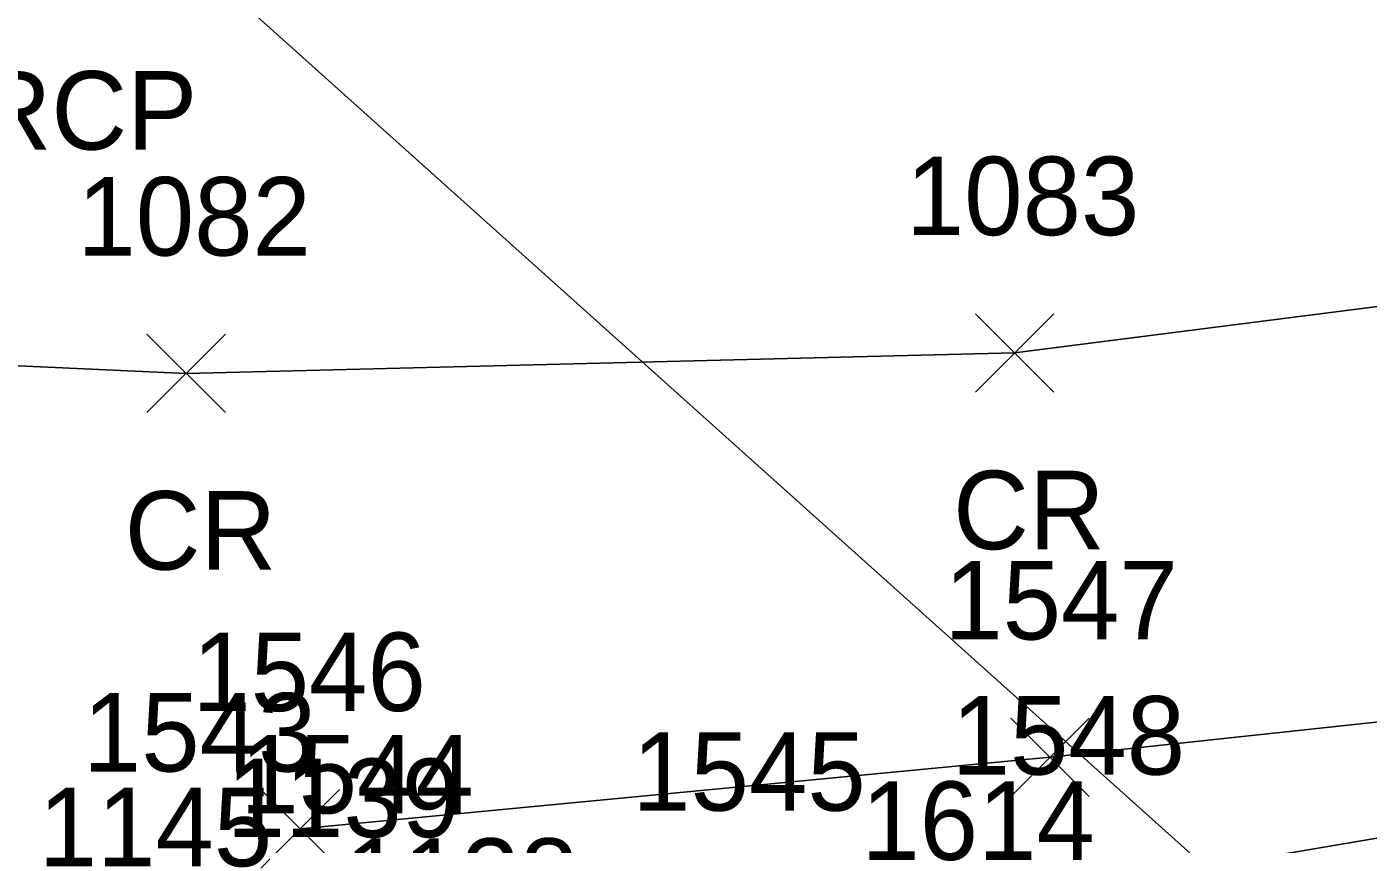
# Model space of a CAD drawing. Extents: x 1657482 to 1661439, y 647981 to 649041.
# Drawn here: x 1659845.16 to 1659879.34, y 648083.85 to 648104.67 of the extents above; entities that cross this region are included whole.
import ezdxf

# ---------------------------------------------------------------- set-up
doc = ezdxf.new("R2010")
doc.units = 0
for name, color, linetype in [('D_C', 7, 'Continuous'), ('DCP', 7, 'Continuous'), ('L_I', 7, 'Continuous'), ('P_A', 7, 'Continuous'), ('P_I', 7, 'Continuous'), ('P_TIC', 7, 'Continuous'), ('PET', 7, 'Continuous'), ('PRC', 7, 'Continuous')]:
    doc.layers.add(name, color=color, linetype=linetype)

msp = doc.modelspace()

# ---------------------------------------------------------------- linework, layer by layer
at = {"layer": 'DCP'}
msp.add_lwpolyline([(1659844.779, 648110.54), (1659890.624, 648069.43)], dxfattribs=at)
at = {"layer": 'P_TIC'}
for points in [[(1659869.331, 648095.361), (1659871.331, 648097.361)], [(1659871.331, 648095.361), (1659869.331, 648097.361)], [(1659848.225, 648094.841), (1659850.225, 648096.841)], [(1659850.225, 648094.841), (1659848.225, 648096.841)], [(1659870.232, 648085.062), (1659872.232, 648087.062)], [(1659872.232, 648085.062), (1659870.232, 648087.062)], [(1659851.129, 648083.239), (1659853.129, 648085.239)], [(1659853.129, 648083.239), (1659851.129, 648085.239)]]:
    msp.add_lwpolyline(points, dxfattribs=at)
at = {"layer": 'PET'}
msp.add_lwpolyline([(1659799.28, 648086.136), (1659822.829, 648084.094), (1659841.236, 648083.238), (1659849.285, 648082.699), (1659853.297, 648081.633), (1659863.28, 648081.701), (1659871.418, 648082.62), (1659885.552, 648085.022), (1659891.684, 648086.345), (1659901.533, 648088.7), (1659915.482, 648092.509), (1659918.893, 648092.262), (1659919.908, 648093.139), (1659925.791, 648090.399), (1659928.096, 648095.554), (1659935.247, 648097.751), (1659946.62, 648102.053), (1659958.358, 648107.252), (1659972.375, 648114.357), (1659985.018, 648121.317), (1659986.135, 648122.233), (1660002.916, 648130.398), (1660023.122, 648141.511)], dxfattribs=at)
at = {"layer": 'PRC'}
for points in [[(1659666.144, 648110.534), (1659699.551, 648107.376), (1659729.526, 648104.331), (1659765.503, 648101.141), (1659792.988, 648098.376), (1659818.732, 648097.206), (1659849.225, 648095.841), (1659870.331, 648096.361), (1659894.597, 648099.456), (1659913.112, 648103.656), (1659935.294, 648110.794), (1659956.941, 648119.929), (1659978.865, 648130.6), (1660002.085, 648142.328), (1660031.609, 648158.263), (1660061.231, 648174.691), (1660097.076, 648195.768), (1660113.884, 648205.485), (1660151.727, 648227.302), (1660188.688, 648248.658)], [(1659852.129, 648084.239), (1659871.232, 648086.062), (1659885.393, 648087.581), (1659901.359, 648090.126), (1659915.349, 648093.34)]]:
    msp.add_lwpolyline(points, dxfattribs=at)

# ---------------------------------------------------------------- texts
at = {"layer": 'D_C'}
msp.add_text('18 RCP', height=2, dxfattribs=at).set_placement((1659840.141, 648101.54))
at = {"layer": 'L_I'}
for s, p in [('1139', (1659850.255, 648084.027)), ('1145', (1659845.467, 648083.286)), ('1138', (1659853.262, 648081.995))]:
    msp.add_text(s, height=2, dxfattribs=at).set_placement(p)
at = {"layer": 'P_A'}
for p in [(1659868.764, 648091.361), (1659847.658, 648090.841)]:
    msp.add_text('CR', height=2, dxfattribs=at).set_placement(p)
at = {"layer": 'P_I'}
for s, p in [('1083', (1659867.56, 648099.361)), ('1082', (1659846.453, 648098.841)), ('1547', (1659868.539, 648089.062)), ('1546', (1659849.381, 648087.239)), ('1543', (1659846.592, 648085.699)), ('1548', (1659868.725, 648085.62)), ('1544', (1659850.604, 648084.633)), ('1544', (1659850.604, 648084.633)), ('1545', (1659860.588, 648084.701)), ('1545', (1659860.588, 648084.701)), ('1614', (1659866.425, 648083.447))]:
    msp.add_text(s, height=2, dxfattribs=at).set_placement(p)

doc.saveas('drawing.dxf')
